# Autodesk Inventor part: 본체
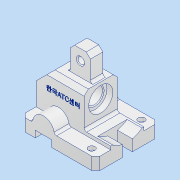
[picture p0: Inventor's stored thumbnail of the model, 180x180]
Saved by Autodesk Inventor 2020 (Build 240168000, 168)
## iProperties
Created: 2022-08
Part Number: 본체
Material: 알루미늄 6061
Document SubType Name: Modeling
Designer: user
Mass: 499.243 g
Surface Area: 337.564 cm^2
Volume: 184.905 cm^3
Density: 2.7 g/cm^3
Appearance: 알루미늄 - 평지
Author: user
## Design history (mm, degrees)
sketch "스케치1"
  geometry: L1 (-41, 18)-(17, 18); L2 (17, 18)-(17, -27); L3 (17, -27)-(-41, -27); L4 (-41, -27)-(-41, 18); L5 (-41, -27)-(49, -27); L6 (49, -27)-(49, -23); L7 (49, -23)-(-41, -23); L8 (-41, -23)-(-41, -27); 3 further points
  constraints: 16 end point, 4 parallel, 2 horizontal, 2 perpendicular
  dimensions: "d1" = 32 distance between parallel lines of L6 L2; "d2" = 90 distance between parallel lines of L4 L6; "d3" = 45 distance between parallel lines of L3 L1; "d4" = 27 distance from line of L5 point (0, 0); "d5" = 17 distance from line of point (0, 0) L2; "d6" = 4 distance of L5.end L6.end
extrude "돌출1" new body sketch "스케치1" stored distance "d7" = 40; taper "d8" = 0 deg
sketch "스케치2"
  geometry: L1 (-41, -27)-(49, -27); L2 (49, -27)-(49, -42); L3 (49, -42)-(-41, -42); L4 (-41, -42)-(-41, -27); L5 (49, -27)-(-41, -27) reference; L6 (49, -23)-(49, -27) reference; C1 r 13 at (-14, -27); 3 further points
  constraints: 8 end point, 2 parallel, 1 centre point, 1 collinear, 1 horizontal, 1 perpendicular, 1 point on line
  dimensions: "d9" = 26 diameter of C1; "d10" = 15 distance between parallel lines of L3 L1; "d11" = 27 distance from line of L4 C1.centre
extrude "돌출2" join sketch "스케치2" stored distance "d12" = 76; taper "d13" = 0 deg
sketch "스케치3"
  geometry: L1 (-12, 48)-(12, 48); L2 (12, 48)-(12, 18); L3 (12, 18)-(-12, 18); L4 (-12, 18)-(-12, 48); L5 (17, 18)-(-41, 18) reference; L6 (17, -23)-(17, 18) reference; 2 further points
  constraints: 8 end point, 2 parallel, 1 horizontal, 1 midpoint, 1 perpendicular, 1 point on line
  dimensions: "d14" = 24 distance of L1.start L1.end; "d15" = 17 distance from line of L6 point (0, 18); "d16" = 30 distance between parallel lines of L5 L1
extrude "돌출3" join sketch "스케치3" stored distance "d17" = 15; taper "d18" = 0 deg
sketch "스케치4"
  geometry: C1 r 10 at (20, 23); 1 further point
  constraints: 1 centre point, 1 coincident
  dimensions: "d19" = 20 diameter of C1
extrude "돌출4" cut sketch "스케치4" extent not by distance; stored distance "d20" = 0; taper "d21" = 0 deg
sketch "스케치5"
  geometry: C1 r 10 at (20, 23) reference; C2 r 14.5 at (20, 23)
  constraints: 1 centre point, 1 coincident
  dimensions: "d22" = 29 diameter of C2
extrude "돌출5" cut sketch "스케치5" distance "d23" = 7; taper "d24" = 0 deg
sketch "스케치6"
  geometry: L1 (-41, -42)-(49, -42) reference; L2 (-24, -42)-(-4, -42); L3 (-4, -42)-(-4, -34); L4 (-4, -34)-(-24, -34); L5 (-24, -34)-(-24, -42); A1 r 13 centre (-14, -27) between (-1, -27) and (-27, -27) reference; 3 further points
  constraints: 8 end point, 2 parallel, 1 horizontal, 1 midpoint, 1 perpendicular, 1 point on line, 1 vertical alignment
  dimensions: "d25" = 20 distance of L3.end L4.end; "d26" = 8 distance of L4.end L2.start
extrude "돌출6" cut sketch "스케치6" extent not by distance; stored distance "d27" = 0; taper "d28" = 0 deg
chamfer "모따기1" distance "d29" = 18; stored, may be unused: second distance "d30" = 2, angle "d31" = 45 deg
sketch "스케치7"
  geometry: L1 (58, -19)-(-18, -19) reference; L2 (14, -19)-(26, -19); L3 (26, -19)-(26, 23); L4 (26, 23)-(14, 23); L5 (14, 23)-(14, -19); C1 r 29 at (20, 23); 7 further points
  constraints: 8 end point, 3 midpoint, 2 coincident, 2 parallel, 1 centre point, 1 horizontal, 1 perpendicular
  dimensions: "d32" = 58 diameter of C1; "d33" = 12 distance of L3.end L4.end
extrude "돌출7" cut sketch "스케치7" distance "d34" = 18; taper "d35" = 0 deg
chamfer "모따기2" distance "d36" = 5; stored, may be unused: second distance "d37" = 2, angle "d38" = 45 deg
sketch "스케치8"
  geometry: L1 (12, 18)-(12, 48) reference; C1 r 4 at (0, 35); 1 further point
  constraints: 1 centre point
  dimensions: "d39" = 8 diameter of C1; "d40" = 12 distance from line of L1 C1.centre; "d41" = 35 distance of point (0, 0) C1.centre
extrude "돌출8" cut sketch "스케치8" extent not by distance; stored distance "d42" = 0; taper "d43" = 0 deg
sketch "스케치9"
  geometry: L1 (50, 53)-(50, 40) reference; L2 (50, 50)-(37, 50); L3 (37, 50)-(37, -10); L4 (37, -10)-(50, -10); L5 (50, -10)-(50, 50); 4 further points
  constraints: 8 end point, 2 coincident, 2 parallel, 1 horizontal, 1 horizontal alignment, 1 midpoint, 1 perpendicular, 1 point on line
  dimensions: "d44" = 60 distance of L4.end L2.start; "d45" = 13 distance of L3.end L4.end
hole "구멍1" sketch "스케치9" at (37, 50), (37, -10) diameter "d46" = 4.5; stored, may be unused: countersink angle "d50" = 60 deg, drill point angle "d52" = 118 deg; dims "d47" = 6, "d48" = 8, "d49" = 4.4, "d51" = 3
fillet "모깎기1" dims "d53" = 3
chamfer "모따기3" distance "d54" = 1; stored, may be unused: second distance "d55" = 2, angle "d56" = 45 deg
node "작업 평면1"
sketch "스케치10"
  geometry: L1 (17, -20)-(17, 13) reference; L2 (17, 18)-(-23, 18) reference; 2 further points
  constraints: 1 other
  dimensions: "d58" = 25 distance from line of L1 point (-8, 0); "d59" = 18 distance from line of L2 point (-8, 0)
feature "엠보싱1" sketch "스케치10" dims "d60" = 0.5, "d61" = 0
node "솔리드1"
feature "A9D066F2-1C7D-4E18-AEED-F7BC21143FA4" dims "d46" = 4.5, "d47" = 6, "d48" = 8, "d49" = 4.4, "d50" = 60 deg, "d51" = 3, "d52" = 118 deg
